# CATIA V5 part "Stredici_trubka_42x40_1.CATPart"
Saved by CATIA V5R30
Part number: Stredici_trubka_42x40_1
Definition: E 1160_42x40_2
Nomenclature: E 1160_42x40_2
Source: Unknown
Description: PART--DESC
Bounding box of the stored display mesh (mm): x -208 to -166, y 116.01 to 157.99, z 90.7 to 130.7
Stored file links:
  E:\Bakalarka\Model\Forma_v7\Stredici_trubka_42x40_1.CATPart
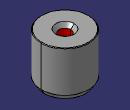
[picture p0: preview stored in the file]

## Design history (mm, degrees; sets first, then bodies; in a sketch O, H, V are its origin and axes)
Body1 "MANIFOLD_SOLID_BREP #3858" (main body)
  Solid1: solid without history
